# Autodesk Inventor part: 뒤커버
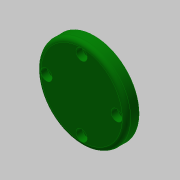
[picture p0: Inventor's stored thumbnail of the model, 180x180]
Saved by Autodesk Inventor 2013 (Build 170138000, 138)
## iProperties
Created: 2019-01
Part Number: 뒤커버
Material: 일반
Document SubType Name: Modeling
Designer: mduedu
Density: 1 g/cm^3
Mass: 27.0088 g
Surface Area: 93.0687 cm^2
Volume: 27.0088 cm^3
Author: mduedu
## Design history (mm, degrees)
sketch "스케치1"
  geometry: L1 (0, 0)-(9, 0); L2 (9, 0)-(9, 32); L3 (9, 32)-(0, 32); L4 (0, 32)-(0, 0); L5 (9, 0)-(12, 0); L6 (12, 0)-(12, 20); L7 (12, 20)-(9, 20); L8 (9, 20)-(9, 0)
  constraints: 16 end point, 4 parallel, 2 horizontal, 2 perpendicular
  dimensions: "d0" = 12 distance between parallel lines of L6 L4; "d2" = 64 diameter of L3 L1; "d3" = 40 diameter of L7 L5; "d4" = 3 distance between parallel lines of L6 L2
revolve "회전1" sketch "스케치1" stored, may be unused: angle "d5" = 90 deg
sketch "스케치4"
  geometry: C1 r 15 at (0, 0); 1 further point
  constraints: 1 centre point, 1 coincident
  dimensions: "d24" = 30 diameter of C1
extrude "돌출1" cut sketch "스케치4" distance "d25" = 6; taper "d26" = 0 deg
fillet "모깎기4" dims "d27" = 3
fillet "모깎기3" dims "d18" = 3
chamfer "모따기2" distance "d28" = 1; stored, may be unused: second distance "d29" = 2, angle "d30" = 45 deg
sketch "스케치3" dims "d19" = 50
  geometry: 6 further points
  constraints: 2 vertical alignment, 1 coincident, 7 other
  dimensions: "d22" = 360 deg dimension on point (0, 0) point (0, 25) (derived)
sketch "스케치5"
  geometry: 4 further points
  constraints: 4 other
hole "구멍1" sketch "스케치5" at (-25, 0), (0, -25), (25, 0), (0, 25) diameter "d31" = 4.5; stored, may be unused: countersink angle "d35" = 90 deg, drill point angle "d37" = 0 deg; dims "d32" = 6, "d33" = 8, "d34" = 4.6, "d36" = 8
node "솔리드1"
